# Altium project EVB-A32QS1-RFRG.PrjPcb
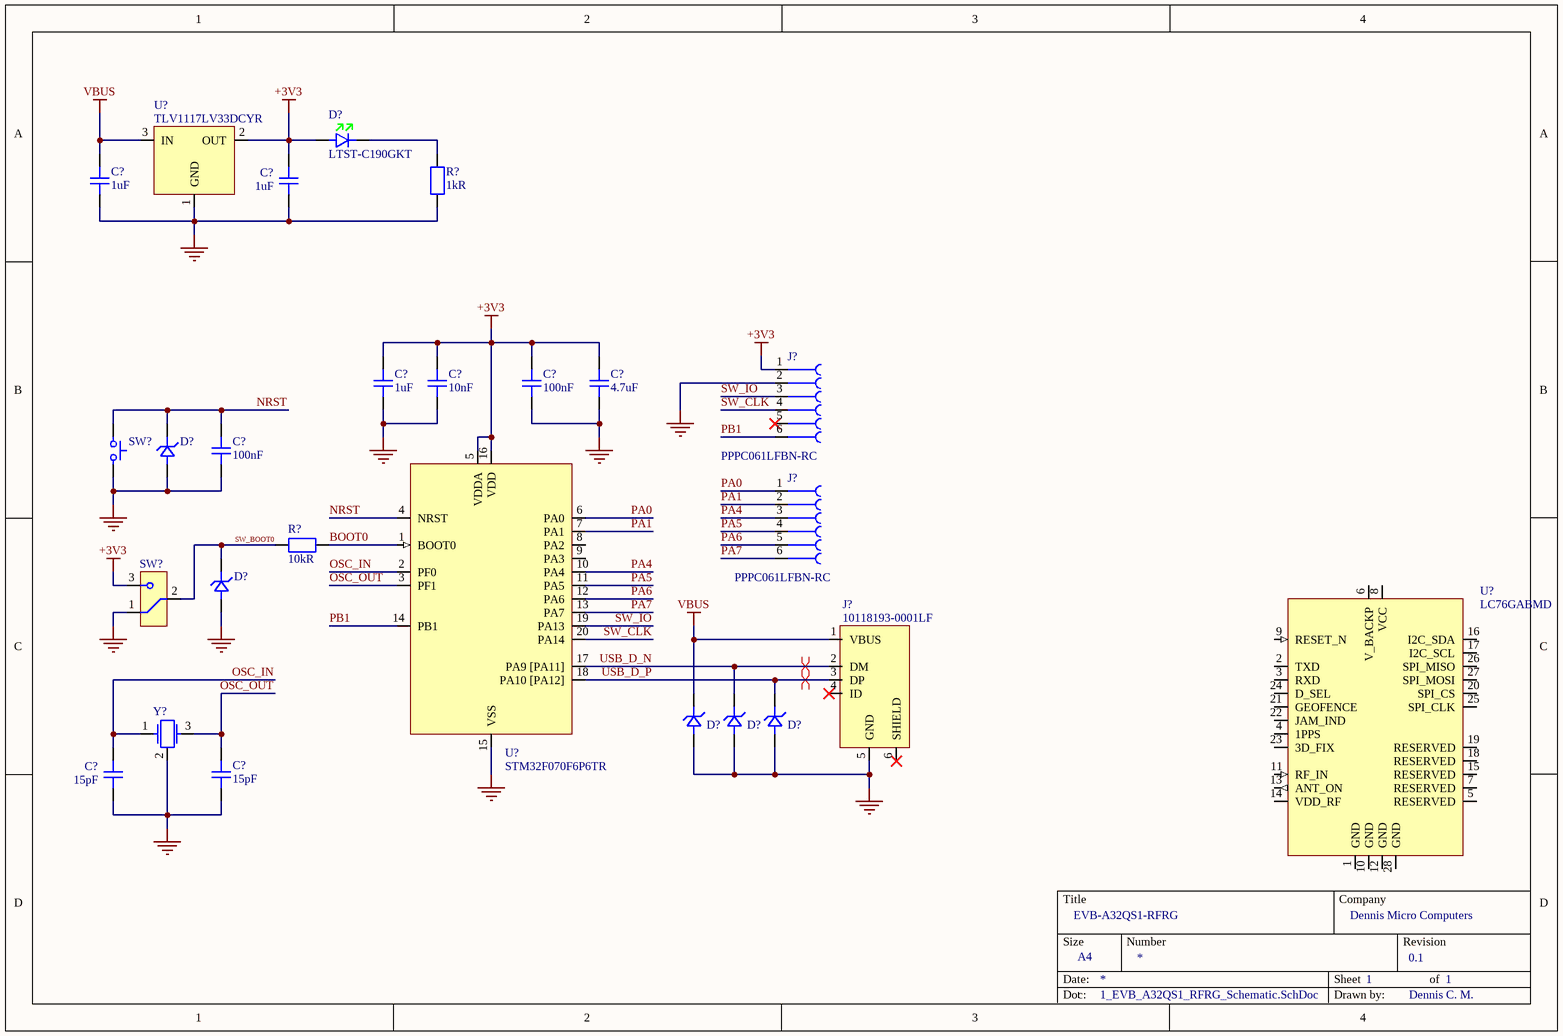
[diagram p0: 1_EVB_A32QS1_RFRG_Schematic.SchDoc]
CompanyName: Dennis Micro Computers; DrawnBy: Dennis C. M.; Revision: 0.1; Title: EVB-A32QS1-RFRG
1 sheet, 26 parts. Net scope: global (net labels, ports and power ports of the same name join across sheets).

## Sheet 1_EVB_A32QS1_RFRG_Schematic.SchDoc: EVB-A32QS1-RFRG
size A4; Author: Dennis C. M; CompanyName: Dennis Micro Computers; DrawnBy: Dennis C. M.; SheetNumber: 1; SheetTotal: 1; Size: A4

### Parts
(Parts that share a designator on the sheet are numbered #1, #2 ... from top to bottom, then left to right.)
C?#1  value 1uF  [C_Yageo_CC_0402_A]  (hidden comment: CC0402MRX5R6BB105)
C?#2  value 1uF  [C_Yageo_CC_0402_A]  (hidden comment: CC0402MRX5R6BB105)
C?#3  value 1uF  [C_Yageo_CC_0402_A]  (hidden comment: CC0402MRX5R6BB105)
C?#4  value 10nF  [C_Yageo_CC_0402_A]  (hidden comment: CC0402KRX7R7BB103)
C?#5  value 100nF  [C_Samsung_CL_0402_A]  (hidden comment: CL05B104KP5NNNC)
C?#6  value 4.7uF  [C_Samsung_CL_0402_A]  (hidden comment: CL05A475MP5NRNC)
C?#7  value 100nF  [C_Samsung_CL_0402_A]  (hidden comment: CL05B104KP5NNNC)
C?#8  value 15pF  [C_Yageo_CC_0402_A]  (hidden comment: CC0402JRNPO9BN150)
C?#9  value 15pF  [C_Yageo_CC_0402_A]  (hidden comment: CC0402JRNPO9BN150)
D?#1  LTST-C190GKT  [D_LED_Lite-On_Green_0603_A]
D?#2  D5V0F1U2S9-7  [D_TVS_Uni_Diodes_SOD-923_B]  (value not drawn)
D?#3  D5V0F1U2S9-7  [D_TVS_Uni_Diodes_SOD-923_B]  (value not drawn)
D?#4  D5V0F1U2S9-7  [D_TVS_Uni_Diodes_SOD-923_B]  (value not drawn)
D?#5  D5V0F1U2S9-7  [D_TVS_Uni_Diodes_SOD-923_B]  (value not drawn)
D?#6  D5V0F1U2S9-7  [D_TVS_Uni_Diodes_SOD-923_B]  (value not drawn)
J?#1  PPPC061LFBN-RC  [J_Sullins_01x06_Socket_2.54mm]
J?#2  PPPC061LFBN-RC  [J_Sullins_01x06_Socket_2.54mm]
J?#3  10118193-0001LF  [J_USB_Micro-B_Amphenol_10118193-0001LF]
R?#1  value 1kR  [R_Yageo_RCL_0402_A]  (hidden comment: RC0402FR-071KL)
R?#2  value 10kR  [R_Yageo_RCL_0402_A]  (hidden comment: RC0402FR-0710KL)
SW?#1  PTS647SN50SMTR2LFS  [SW_Tactitle_SPST_C&K_PTS647SN50SMTR2LFS]  (value not drawn)
SW?#2  JS102011JCQN  [SW_Slide_C&K_JS102011JCQN]  (value not drawn)
U?#1  TLV1117LV33DCYR  [U_TI_SOT-223_B]
U?#2  STM32F070F6P6TR  [U_ST_TSSOP20_B]
U?#3  LC76GABMD  [U_QUECTEL_LC76G]
Y?  ECS-240-12-37B-CKY-TR  [Y_Crystal_GND24_ECS_240-12-37B-CKY-TR]  (value not drawn)

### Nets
+3V3: C?#2.2 C?#3.2 C?#4.2 C?#5.2 C?#6.2 D?#1.2 J?#1.1 SW?#2.3 U?#1.2(OUT) U?#2.5(VDDA) U?#2.16(VDD)
GND: C?#1.1 C?#2.1 C?#3.1 C?#4.1 C?#5.1 C?#6.1 C?#7.1 C?#8.1 C?#9.1 D?#2.2 D?#3.2 D?#4.2 D?#5.2 D?#6.2 J?#1.2 J?#3.5(GND) R?#1.1 SW?#1.2 SW?#2.1 U?#1.1(GND) U?#2.15(VSS) Y?.2
VBUS: C?#1.2 D?#4.1 J?#3.1(VBUS) U?#1.3(IN)
BOOT0: R?#2.2 U?#2.1(BOOT0)
NRST: C?#7.2 D?#2.1 SW?#1.1 U?#2.4(NRST)
OSC_IN: C?#8.2 U?#2.2(PF0) Y?.1
OSC_OUT: C?#9.2 U?#2.3(PF1) Y?.3
PA0: J?#2.1 U?#2.6(PA0)
PA1: J?#2.2 U?#2.7(PA1)
PA4: J?#2.3 U?#2.10(PA4)
PA5: J?#2.4 U?#2.11(PA5)
PA6: J?#2.5 U?#2.12(PA6)
PA7: J?#2.6 U?#2.13(PA7)
PB1: J?#1.6 U?#2.14(PB1)
SW_BOOT0: D?#3.1 R?#2.1 SW?#2.2
SW_CLK: J?#1.4 U?#2.20(PA14)
SW_IO: J?#1.3 U?#2.19(PA13)
USB_D_N: D?#5.1 J?#3.2(DM) U?#2.17(PA9_[PA11])
USB_D_P: D?#6.1 J?#3.3(DP) U?#2.18(PA10_[PA12])
NetD?#1_1: D?#1.1 R?#1.2

Not connected (* = marked no-connect by the designer): J?#1 5*; J?#3 4(ID)* 6(SHIELD)*; U?#2 8(PA2) 9(PA3); U?#3 1(GND) 2(TXD) 3(RXD) 4(1PPS) 5(RESERVED) 6(V_BACKP) 7(RESERVED) 8(VCC) 9(RESET_N) 10(GND) 11(RF_IN) 12(GND) 13(ANT_ON) 14(VDD_RF) 15(RESERVED) 16(I2C_SDA) 17(I2C_SCL) 18(RESERVED) 19(RESERVED) 20(SPI_CS) 21(GEOFENCE) 22(JAM_IND) 23(3D_FIX) 24(D_SEL) 25(SPI_CLK) 26(SPI_MISO) 27(SPI_MOSI) 28(GND)

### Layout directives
differential pair; differential pair class DIFF_USB: USB_D_N, USB_D_P

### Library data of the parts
C?#1-C?#3 = CMP-001-00016-11: Multilayer Ceramic Capacitor, 1 uF, 50 V, ± 10%, X5R, 0402 [1005 Metric]; Voltage Rating (DC): 10V; Tolerance: 20%; Temperature Coefficient: 30ppm/°C
C?#4 = CMP-001-00029-1: Multilayer Ceramic Capacitor, 0.01 uF, 16 V, ± 10%, X7R, 0402 [1005 Metric]; Dissipation Factor: 3.5%; Voltage Rating: 16V; Temperature Coefficient: 30ppm/°C; Insulation Resistance: 10GR
C?#5 C?#7 = CMP-001-00023-3: Multilayer Ceramic Capacitor, 0.1 uF, 10 V, ± 10%, X7R, 0402 [1005 Metric]; Voltage Rating (DC): 10V
C?#6 = CMP-001-00024-3: Multilayer Ceramic Capacitor, 4.7 uF, 10 V, ± 20%, X5R, 0402 [1005 Metric]; Voltage Rating: 10V
C?#8 C?#9 = CMP-001-00017-14: Multilayer Ceramic Capacitor, 15 pF, 10 V, ± 5%, X7R, 0402 [1005 Metric]; Temperature Coefficient: 30ppm/°C; Voltage Rating (DC): 50V; Dielectric: C0G; Insulation Resistance: 100GR
D?#1 = CMP-007-00001-3: LED Uni-Color Green 565nm 2-Pin Chip LED T/R; Dominant Wavelength: 569nm; Forward Current: 30mA; Reverse Voltage: 5V; Lens Transparency: Clear; Power Dissipation: 100mW; Number of Elements: 1; Viewing Angle: 130°; Test Current: 10mA; Forward Voltage: 2.1V; Lens Color: Colorless; Voltage: 2V; Lens Size: 0.8mm; Lens Style: Flat,Diffused,Colorless,Rectangular,Clear; Luminous Intensity: 6mcd
D?#2-D?#6 = CMP-004-00007-2: Diode TVS Dual Uni-Dir 5.5V 250000W 2-Pin SOD-923 T/R; Max Reverse Leakage Current: 100nA; Number of Unidirectional Channels: 1; ESD Protection: Yes; Diode Type: ZENER; Max Surge Current: 1.5A; Min Breakdown Voltage: 6V; Polarity: Unidirectional; Value: 5E-13F; Max Power Dissipation: 250mW; Clamping Voltage: 10V; Peak Pulse Power: 250kW
J?#1 J?#2 = CMP-002-00006-3: 6 Position Header Connector 0.100 (2.54mm) Through Hole Gold"; Number of Positions: 6; Voltage Rating: 250V; Current Rating: 3A
J?#3 = CMP-002-00002-12: Usb Connector, 5 Contact(S), Female, Right Angle, Surface Mount Terminal, Locking, Receptacle; Max Voltage Rating (AC): 100V; USB Standard: USB 2.0; Connector Type: USB,Receptacle; Number of Contacts: 5; Number of Ports: 1; Insulation Resistance: 1GR; Pitch: 650um; Current Rating: 1.8A
R?#1 = CMP-009-00002-11: SMD Chip Resistor, 1 kOhm, ± 1%, 62.5 mW, 0402 [1005 Metric], Thick Film, General Purpose; Max Power Dissipation: 63mW; Temperature Coefficient: 100ppm/°C; Voltage Rating (AC): 50V; Power Rating: 62.5mW
R?#2 = CMP-009-00003-11: SMD Chip Resistor, 10 kOhm, ± 1%, 62.5 mW, 0402 [1005 Metric], Thick Film, General Purpose; Voltage Rating (DC): 50V; Temperature Coefficient: 100ppm/°C; Power Rating: 62.5mW; Max Power Dissipation: 63mW
SW?#1 = CMP-011-00000-13: Switch Tactile N.O. SPST Round Button Gull Wing 0.05A 12VDC 100000Cycles 0.98N SMD T/R; pin to pad: 1>1+2 2>3+4; Number of Positions: 2; Operating Force: 100gf; Actuator Type: Standard; Illumination Type: Non-Illuminated; Switch Function: Off-Mom; Switch Travel: 0.25mm; Ratings: IP40
SW?#2 = CMP-011-00001-10: JS Series Sub-Miniature Slide Switch SPDT On-On Top Slide 0.3A 6VDC J-Lead Surface Mount T/R; Actuator Type: Standard; Switch Travel: 2mm; Actuator Material: Nylon,Polyamide,PA46; Voltage Rating (DC): 6V; Electrical Life: 5000Cycles
U?#1 = CMP-019-00002-1: LDO Regulator Pos 3.3V 1A 4-Pin(3+Tab) SOT-223 T/R; Output Type: Fixed; Power Supply Rejection Ratio (PSRR): 75dB; Polarity: Positive; Dropout Voltage: 570mV; Quiescent Current: 50uA; Max Supply Voltage: 5.5V; Accuracy: 2%; Number of Regulators: 1; Min Input Voltage: 2V
U?#2 = CMP-020-00001-4: IC MCU 32BIT 32KB FLASH 20TSSOP; Core Architecture: ARM; Oscillator Type: Internal; Number of I/Os: 15; Peripherals: POR,PWM,WDT,DMA; Interface: I2C,SPI,USB,UART,USART
U?#3 = CMP-00025-00000-1: Navigation BeiDou, Galileo, GLONASS, GPS, GNSS Transceiver Module 1.561GHz, 1.575GHz, 1.602GHz Antenna Not Included Surface Mount; Serial Interfaces: I2C, UART; Sensivity: -166dBm; Supply Voltage: 2.55V ~ 3.6V
Y? = CMP-003-00000-10: Crystal 24MHz ±10ppm (Tol) ±10ppm (Stability) 12pF FUND 50Ohm 4-Pin Mini-CSMD T/R; pin to pad: 2>2+4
